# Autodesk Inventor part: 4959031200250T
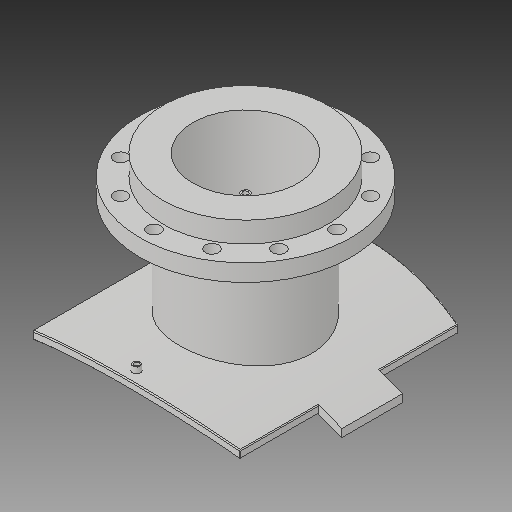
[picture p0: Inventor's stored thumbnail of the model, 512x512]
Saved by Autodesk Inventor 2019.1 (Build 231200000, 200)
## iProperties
Created: 2017-10
Part Number: 4959031200250T
Material: Generic
Description: PLASSON FLANGED BRANCH SADDLE 1200X250
Document SubType Name: Modeling
Designer: KIM
Mass: 2339.99 g
Surface Area: 3251.55 cm^2
Volume: 2339.99 cm^3
Density: 1 g/cm^3
Appearance: Default
Author: KIM
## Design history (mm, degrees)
derived "495904_495903.ipt"
feature "Solid1::495904_495903.ipt"
feature "Solid2::495904_495903.ipt"
tag "TaggingFeature1"
body "Solid1"
other parameters: "d1" = 15, "d2" = 402.3, "d4" = 0, "d6" = 117.5, "d7" = 0, "d12" = 625.6, "d13" = 14, "d14" = 211.5, "d16" = 5 deg, "d18" = 4, "d19" = 14, "d20" = 0, "d21" = 3, "d22" = 0, "d36" = 211.5, "d38" = 0, "d39" = 2, "d41" = 204, "d46" = 256, "d47" = 16, "d48" = 10.4, "d49" = 192.5, "d51" = 1224, "d53" = 0, "d54" = 26, "d55" = 177.5, "d57" = 0, "d59" = 360 deg, "d61" = 33, "d63" = 0, "d66" = 275, "d67" = 15, "d68" = 137.5, "d70" = 0, "d71" = 2, "d72" = 447, "B_" = 447, "H_" = 275, "x_" = 15, "D_" = 16, "DN_" = 204, "t_" = 33, "s_" = 26, "Dp_" = 355
